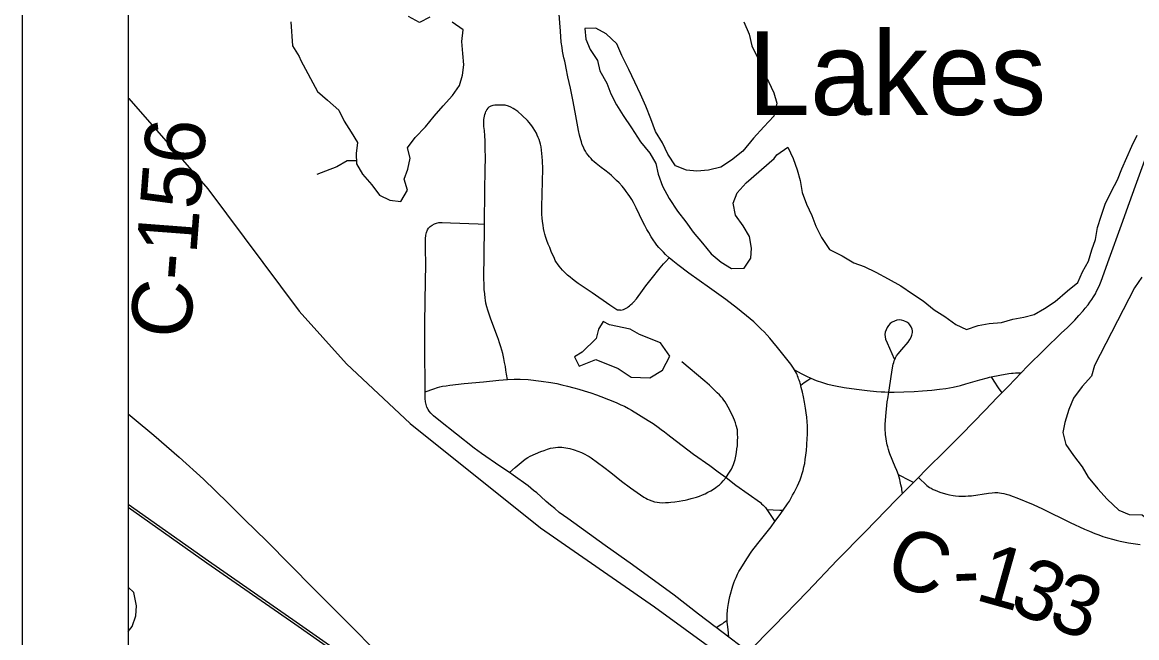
# Model space of a CAD drawing. Extents: x 0 to 34, y 0 to 22.
# Drawn here: x 2.014 to 3.067, y 16.327 to 16.909 of the extents above; entities that cross this region are included whole.
import ezdxf

# ---------------------------------------------------------------- set-up
doc = ezdxf.new("R2010")
doc.units = 0
for name, color, linetype in [('GM_X_Corporation', 7, 'Continuous'), ('GM_X_County_Road', 7, 'Continuous'), ('GM_X_County_Road_Text', 7, 'Continuous'), ('GM_X_Minor_Lake', 7, 'Continuous'), ('GM_X_Minor_River', 7, 'Continuous'), ('GM_X_Rail_Line', 7, 'Continuous'), ('GM_X_State_Route', 7, 'Continuous'), ('GM_X_Township_Road', 7, 'Continuous'), ('GM_X_Unincorporated_Text', 7, 'Continuous'), ('SH_Data', 7, 'Continuous')]:
    doc.layers.add(name, color=color, linetype=linetype)

msp = doc.modelspace()

# ---------------------------------------------------------------- linework, layer by layer
at = {"layer": 'GM_X_Corporation'}
msp.add_lwpolyline([(4.732, 17.2135), (3.7259, 17.2107), (3.5941, 17.2097), (3.4848, 17.2088), (3.0597, 17.2067), (2.6493, 17.2102), (2.5952, 17.2097), (2.159, 17.2055), (2.114, 17.2048), (2.114, 13.8173), (5.0539, 13.8173)], dxfattribs=at)
at = {"layer": 'GM_X_County_Road'}
for points in [[(2.114, 16.5387), (2.1198, 16.5341), (2.1385, 16.5187), (2.1622, 16.4977), (2.1852, 16.477), (2.2083, 16.4546), (2.2242, 16.439), (2.2452, 16.4184), (2.2893, 16.3739), (2.3285, 16.3343), (2.3433, 16.3193)], [(2.8611, 16.4786), (2.869, 16.4712), (2.8716, 16.4693), (2.873, 16.4685), (2.875, 16.4674), (2.8769, 16.4666), (2.879, 16.4657), (2.8813, 16.4649), (2.8844, 16.4638), (2.8879, 16.4629), (2.8905, 16.4622), (2.8937, 16.4616), (2.8961, 16.4612), (2.8993, 16.461), (2.9011, 16.4609), (2.9035, 16.4609), (2.9055, 16.4609), (2.908, 16.4612), (2.9112, 16.4614), (2.9272, 16.4638), (2.9307, 16.4641), (2.9333, 16.4644), (2.936, 16.4643), (2.9375, 16.4642), (2.9395, 16.4639), (2.9417, 16.4635), (2.944, 16.4628), (2.9464, 16.4622), (2.9504, 16.4607), (2.9539, 16.4594), (2.9694, 16.4531), (2.9784, 16.4489), (3.0044, 16.4361), (3.018, 16.4299), (3.0228, 16.4279), (3.0277, 16.4258), (3.0316, 16.4244), (3.0354, 16.423), (3.0398, 16.4217), (3.0443, 16.4203), (3.0478, 16.4194), (3.0516, 16.4185), (3.0565, 16.4176), (3.0595, 16.417), (3.0662, 16.4159), (3.0706, 16.4152)]]:
    msp.add_lwpolyline(points, dxfattribs=at)
at = {"layer": 'GM_X_Minor_Lake'}
for p, q in [((2.2772, 16.8725), (2.2929, 16.8434)), ((2.6982, 16.7571), (2.7245, 16.78)), ((3.0653, 16.6579), (3.0273, 16.5844)), ((2.5563, 16.61), (2.5431, 16.597))]:
    msp.add_line(p, q, dxfattribs=at)
for points in [[(2.2678, 16.9092), (2.2695, 16.8865), (2.2756, 16.8763), (2.2772, 16.8725)], [(2.2929, 16.8434), (2.3024, 16.8351), (2.3131, 16.8257), (2.3181, 16.8152), (2.325, 16.805), (2.3308, 16.7952), (2.3297, 16.7849), (2.3298, 16.7751), (2.3355, 16.7652), (2.3443, 16.7551), (2.3516, 16.7453), (2.3615, 16.7408), (2.3717, 16.7394), (2.378, 16.75), (2.3749, 16.7606), (2.3783, 16.7701), (2.3805, 16.7804), (2.3781, 16.7902), (2.3852, 16.7998), (2.395, 16.8101), (2.4032, 16.82), (2.4119, 16.8299), (2.4205, 16.8395), (2.4272, 16.849), (2.4302, 16.8589), (2.4312, 16.8684), (2.4304, 16.8794), (2.4296, 16.8907), (2.4306, 16.9017), (2.4203, 16.9089)], [(2.3991, 16.9136), (2.3893, 16.9086), (2.379, 16.9142)], [(2.6959, 16.9091), (2.7009, 16.8974), (2.7036, 16.8864), (2.709, 16.8754), (2.7133, 16.8626), (2.7194, 16.8528), (2.7244, 16.8422), (2.7271, 16.8324), (2.7242, 16.8202), (2.7148, 16.8099), (2.705, 16.7992), (2.6949, 16.787), (2.6844, 16.7786), (2.6742, 16.772), (2.6625, 16.7689), (2.6515, 16.7681), (2.6417, 16.7691), (2.6314, 16.7732), (2.6242, 16.7842), (2.6192, 16.7947), (2.6126, 16.8057), (2.608, 16.8174), (2.6034, 16.8295), (2.5984, 16.8408), (2.593, 16.8522), (2.5872, 16.8643), (2.5807, 16.8775), (2.576, 16.8885), (2.5658, 16.8979), (2.5562, 16.9031), (2.5457, 16.903), (2.5465, 16.8928), (2.5507, 16.8829), (2.5576, 16.8728), (2.56, 16.8629), (2.5665, 16.8512), (2.5704, 16.841), (2.5757, 16.8308), (2.5819, 16.8206), (2.5899, 16.8089), (2.5983, 16.7957), (2.6071, 16.7852), (2.6129, 16.7754), (2.6149, 16.7651), (2.6191, 16.7538), (2.6253, 16.7421), (2.6333, 16.7304), (2.6413, 16.7202), (2.6482, 16.7104), (2.657, 16.6999), (2.665, 16.6901), (2.6745, 16.6822), (2.6844, 16.6762), (2.6962, 16.6763), (2.7025, 16.6858), (2.7032, 16.6953), (2.7012, 16.7063), (2.6955, 16.7165), (2.6882, 16.7266), (2.6858, 16.738), (2.6896, 16.7475), (2.6982, 16.7571)], [(2.7245, 16.78), (2.7271, 16.7834), (2.7377, 16.7907), (2.7427, 16.7802), (2.7465, 16.7692), (2.7493, 16.7593), (2.7512, 16.748), (2.7551, 16.737), (2.7601, 16.7261), (2.764, 16.7162), (2.7694, 16.7053), (2.777, 16.694), (2.7888, 16.688), (2.7998, 16.6816), (2.8097, 16.6779), (2.8207, 16.6727), (2.8325, 16.6663), (2.8443, 16.6596), (2.8553, 16.6521), (2.8656, 16.6457), (2.8759, 16.6371), (2.8861, 16.6307), (2.8964, 16.6232), (2.9063, 16.6184), (2.9176, 16.6222), (2.9278, 16.6242), (2.9396, 16.6251), (2.9501, 16.6282), (2.9607, 16.6302), (2.9705, 16.6325), (2.9803, 16.6383), (2.9901, 16.6448), (3.0018, 16.6551), (3.0115, 16.6628), (3.016, 16.6731), (3.0216, 16.683), (3.0249, 16.6936), (3.0283, 16.7035), (3.0301, 16.7149), (3.0338, 16.7255), (3.0375, 16.7369), (3.0434, 16.7491), (3.049, 16.7598), (3.0531, 16.7704), (3.0628, 16.7917), (3.0676, 16.802)], [(3.0721, 16.6678), (3.0653, 16.6579)], [(2.5431, 16.597), (2.536, 16.5927), (2.5402, 16.5837), (2.556, 16.5902), (2.5773, 16.5817), (2.5895, 16.5734), (2.6073, 16.5728), (2.619, 16.5801), (2.626, 16.5934), (2.6172, 16.6059), (2.5975, 16.6137), (2.5887, 16.6189), (2.569, 16.623), (2.563, 16.6259), (2.5585, 16.6187), (2.5563, 16.61)], [(3.0273, 16.5844), (3.0247, 16.5745), (3.0157, 16.5646), (3.0075, 16.5535), (3.003, 16.5429), (2.9993, 16.5307), (2.9975, 16.5212), (3.0003, 16.5099), (3.0075, 16.4993), (3.0156, 16.4888), (3.0213, 16.479), (3.0305, 16.468), (3.0393, 16.4582), (3.0503, 16.4477), (3.0602, 16.4436), (3.0723, 16.4433), (3.0818, 16.4354), (3.0902, 16.4256), (3.0998, 16.4159), (3.1096, 16.4209)], [(2.114, 16.3332), (2.1179, 16.3377), (2.1212, 16.348), (2.1219, 16.3575), (2.1195, 16.37), (2.114, 16.375)]]:
    msp.add_lwpolyline(points, dxfattribs=at)
at = {"layer": 'GM_X_Minor_River'}
msp.add_lwpolyline([(2.3298, 16.7778), (2.3211, 16.778), (2.3113, 16.7723), (2.3007, 16.768), (2.2924, 16.7649)], dxfattribs=at)
at = {"layer": 'GM_X_Rail_Line'}
for points in [[(2.114, 16.8374), (2.1146, 16.8368), (2.1893, 16.7514), (2.2758, 16.6359), (2.3204, 16.5861), (2.3807, 16.5296), (2.5039, 16.4312), (2.6114, 16.3563), (2.7019, 16.2907), (2.7727, 16.25), (2.8225, 16.2263), (2.8815, 16.2027), (2.9759, 16.1869), (3.0752, 16.1606), (3.1383, 16.1243), (3.1826, 16.0961), (3.2121, 16.0625), (3.2578, 15.9657), (3.3033, 15.8368), (3.3342, 15.7629), (3.3516, 15.736), (3.4899, 15.62), (3.595, 15.5619), (3.6872, 15.5056)], [(3.6294, 15.4901), (3.5355, 15.5355), (3.4316, 15.5858), (3.3592, 15.6216), (3.2797, 15.6606), (3.2212, 15.6921), (3.1764, 15.7179), (3.1549, 15.731), (3.1291, 15.7467), (3.1033, 15.7631), (3.0624, 15.7903), (2.916, 15.893), (2.8198, 15.9595), (2.7679, 15.9959), (2.7008, 16.0427), (2.5976, 16.1149), (2.4486, 16.2192), (2.3494, 16.2884), (2.273, 16.3419), (2.1899, 16.3996), (2.114, 16.453)], [(3.6283, 15.488), (3.5345, 15.5334), (3.4306, 15.5837), (3.3582, 15.6195), (3.2786, 15.6585), (3.22, 15.6901), (3.1752, 15.7159), (3.1537, 15.729), (3.1279, 15.7448), (3.1021, 15.7611), (3.0611, 15.7884), (2.9146, 15.8911), (2.8185, 15.9575), (2.7665, 15.994), (2.6995, 16.0408), (2.5963, 16.113), (2.4473, 16.2173), (2.348, 16.2865), (2.2716, 16.34), (2.1886, 16.3977), (2.114, 16.4502)]]:
    msp.add_lwpolyline(points, dxfattribs=at)
at = {"layer": 'GM_X_State_Route'}
msp.add_lwpolyline([(2.7003, 16.3139), (2.7244, 16.3383), (2.7562, 16.371), (2.7843, 16.4004), (2.8107, 16.4274), (2.8404, 16.4577), (2.846, 16.4634), (2.8563, 16.4738), (2.8611, 16.4786), (2.8681, 16.4858), (2.8871, 16.5049), (2.9018, 16.5193), (2.9242, 16.5424), (2.9355, 16.5542), (2.9398, 16.5585), (2.9461, 16.5649), (2.9582, 16.5775), (2.9641, 16.5837), (2.9962, 16.6152), (3.0017, 16.6202), (3.0087, 16.6273), (3.0127, 16.6317), (3.0166, 16.636), (3.0186, 16.6385), (3.0213, 16.6418), (3.0231, 16.6443), (3.025, 16.6469), (3.0265, 16.6494), (3.0282, 16.6523), (3.0294, 16.6547), (3.0308, 16.6574), (3.0323, 16.6609), (3.0337, 16.6643), (3.0413, 16.6854), (3.053, 16.7175), (3.0605, 16.7386), (3.0663, 16.7543), (3.0787, 16.7888)], dxfattribs=at)
at = {"layer": 'GM_X_Township_Road'}
for p, q in [((2.7177, 16.4483), (2.7254, 16.437)), ((2.6818, 16.3278), (2.6699, 16.3368))]:
    msp.add_line(p, q, dxfattribs=at)
for points in [[(2.5943, 16.7334), (2.593, 16.736), (2.5916, 16.7385), (2.5901, 16.7414), (2.5883, 16.7441), (2.5867, 16.7465), (2.5849, 16.7489), (2.5834, 16.7509), (2.5809, 16.7538), (2.5781, 16.757), (2.5756, 16.7594), (2.5737, 16.7613), (2.5708, 16.7639), (2.5687, 16.7658), (2.5647, 16.7689), (2.5613, 16.7716), (2.5564, 16.7754), (2.5545, 16.777), (2.5531, 16.7783), (2.5516, 16.7799), (2.55, 16.7815), (2.5489, 16.7831), (2.5474, 16.7851), (2.5462, 16.7871), (2.5451, 16.789), (2.5443, 16.7909), (2.5433, 16.793), (2.5425, 16.7957), (2.5418, 16.7978), (2.5408, 16.8022), (2.5398, 16.8064), (2.5372, 16.8205), (2.5347, 16.8339), (2.5321, 16.8466), (2.5298, 16.8572), (2.5282, 16.8653), (2.5274, 16.8689), (2.5267, 16.8719), (2.526, 16.8751), (2.5253, 16.8784), (2.5247, 16.8815), (2.5242, 16.8848), (2.5235, 16.89), (2.5226, 16.9003), (2.521, 16.9201)], [(2.451, 16.718), (2.4513, 16.75), (2.4516, 16.769), (2.4517, 16.7813), (2.4517, 16.7839), (2.4516, 16.7863), (2.4516, 16.7892), (2.4515, 16.7927), (2.4514, 16.7969), (2.4512, 16.8016), (2.4508, 16.8064), (2.4504, 16.8103), (2.4503, 16.8154), (2.4503, 16.8169), (2.4505, 16.8185), (2.4508, 16.8202), (2.4511, 16.8216), (2.4517, 16.8232), (2.4522, 16.8246)], [(2.5795, 16.6368), (2.5781, 16.6368), (2.5767, 16.6369), (2.5759, 16.6372), (2.5751, 16.6376), (2.5741, 16.6383), (2.5693, 16.6416), (2.5525, 16.6532), (2.5395, 16.6619), (2.5368, 16.6639), (2.5341, 16.6659), (2.5318, 16.6678), (2.5294, 16.6698), (2.5268, 16.6724), (2.5246, 16.6746), (2.5231, 16.6763), (2.5214, 16.6783), (2.5198, 16.6805), (2.5189, 16.6818), (2.5178, 16.6838), (2.5169, 16.6855), (2.5139, 16.6923), (2.5125, 16.6958), (2.5112, 16.6991), (2.5098, 16.7026), (2.5089, 16.7055), (2.508, 16.7085), (2.5074, 16.7112), (2.5068, 16.7138), (2.5063, 16.7171), (2.5058, 16.7205), (2.5055, 16.7241), (2.5052, 16.7272), (2.5052, 16.7305), (2.5051, 16.7345), (2.5059, 16.7703), (2.5058, 16.7779), (2.5055, 16.7815), (2.5052, 16.7847), (2.5047, 16.788), (2.5043, 16.791), (2.5037, 16.7935), (2.5031, 16.7959), (2.5024, 16.7981), (2.5017, 16.8), (2.5008, 16.8021), (2.4999, 16.8041), (2.4985, 16.8065), (2.497, 16.809), (2.4957, 16.8108), (2.4945, 16.8126), (2.4931, 16.8142), (2.4915, 16.816), (2.4866, 16.8208), (2.4823, 16.8246), (2.4797, 16.8264), (2.4779, 16.8274), (2.4759, 16.8286), (2.4735, 16.8295), (2.4704, 16.8303), (2.4671, 16.8306), (2.4649, 16.8306), (2.4628, 16.8306), (2.4605, 16.8304), (2.4588, 16.83), (2.4569, 16.8295), (2.4551, 16.8286), (2.454, 16.8277), (2.453, 16.8263), (2.4522, 16.8246)], [(2.6255, 16.6863), (2.6221, 16.6894), (2.62, 16.6914), (2.6177, 16.6939), (2.6158, 16.696), (2.6139, 16.6983), (2.6126, 16.6999), (2.6102, 16.7033), (2.6084, 16.7061), (2.6061, 16.71), (2.6043, 16.7131), (2.6023, 16.7169), (2.6005, 16.7203), (2.5943, 16.7334)], [(2.3948, 16.5596), (2.3947, 16.5629), (2.3946, 16.6003), (2.3944, 16.6236), (2.3948, 16.6459), (2.3954, 16.6804), (2.3952, 16.6943), (2.3951, 16.7043), (2.3955, 16.7075), (2.3961, 16.7101), (2.397, 16.7125), (2.3981, 16.7142), (2.3994, 16.7157), (2.4015, 16.7172), (2.4037, 16.7184), (2.4056, 16.7191), (2.4076, 16.7195), (2.4108, 16.7196), (2.4189, 16.7193), (2.4449, 16.7183), (2.451, 16.718)], [(2.4727, 16.5713), (2.4718, 16.5763), (2.4712, 16.5801), (2.4706, 16.5836), (2.4699, 16.5873), (2.4692, 16.591), (2.4681, 16.5958), (2.4673, 16.5989), (2.4664, 16.602), (2.4651, 16.6058), (2.4641, 16.609), (2.4631, 16.6117), (2.4568, 16.6283), (2.4541, 16.6366), (2.4532, 16.64), (2.4523, 16.6433), (2.4518, 16.6461), (2.4515, 16.6482), (2.4511, 16.6522), (2.4507, 16.6563), (2.4505, 16.6614), (2.4503, 16.6662), (2.4509, 16.7136), (2.451, 16.718)], [(2.5795, 16.6368), (2.581, 16.6371), (2.5823, 16.6374), (2.5834, 16.6379), (2.5848, 16.6385), (2.5859, 16.6392), (2.5868, 16.6399), (2.5878, 16.6407), (2.589, 16.6417), (2.5904, 16.6431), (2.5917, 16.6444), (2.5946, 16.6476), (2.6001, 16.6552), (2.6035, 16.6597), (2.6085, 16.666), (2.617, 16.6767), (2.6202, 16.6805), (2.6219, 16.6824), (2.6255, 16.6863)], [(2.7439, 16.5803), (2.7429, 16.5819), (2.7416, 16.5838), (2.7403, 16.5856), (2.7391, 16.5872), (2.7365, 16.5904), (2.7279, 16.6014), (2.7235, 16.6067), (2.7204, 16.6104), (2.718, 16.6132), (2.7151, 16.6164), (2.7124, 16.6189), (2.7084, 16.6229), (2.7054, 16.6256), (2.702, 16.6286), (2.69, 16.6384), (2.6791, 16.6467), (2.6635, 16.6579), (2.6439, 16.6717), (2.6337, 16.6796), (2.6289, 16.6835), (2.6255, 16.6863)], [(2.833, 16.5594), (2.8336, 16.5633), (2.8362, 16.5803), (2.8372, 16.5858), (2.8377, 16.5874), (2.8381, 16.5888), (2.8386, 16.59), (2.8394, 16.5917), (2.8404, 16.5935), (2.8418, 16.5954), (2.8452, 16.5996), (2.8512, 16.6066), (2.8529, 16.609), (2.854, 16.6111), (2.8548, 16.6132), (2.8553, 16.6155), (2.8553, 16.6172), (2.8551, 16.6189), (2.8542, 16.621), (2.853, 16.623), (2.8519, 16.6242), (2.85, 16.6254), (2.8473, 16.6267), (2.8451, 16.6273), (2.8428, 16.6275), (2.8406, 16.6272), (2.8383, 16.6265), (2.8363, 16.6255), (2.8344, 16.6241), (2.8328, 16.6224), (2.8315, 16.6204), (2.8304, 16.6183), (2.8297, 16.6161), (2.8294, 16.6138), (2.8295, 16.6115), (2.83, 16.6092), (2.8314, 16.6059), (2.8359, 16.5957), (2.8381, 16.5908)], [(2.6792, 16.4787), (2.6813, 16.4818), (2.6832, 16.4846), (2.6843, 16.4866), (2.6853, 16.4888), (2.6861, 16.4908), (2.6869, 16.4928), (2.6878, 16.4957), (2.6884, 16.4988), (2.689, 16.5022), (2.6895, 16.5057), (2.6899, 16.5087), (2.6901, 16.5133), (2.6902, 16.5168), (2.6901, 16.5193), (2.6901, 16.5213), (2.6899, 16.5236), (2.6888, 16.5277), (2.688, 16.5302), (2.6871, 16.5329), (2.6861, 16.5351), (2.6849, 16.538), (2.6812, 16.5451), (2.6796, 16.5479), (2.6782, 16.5502), (2.6771, 16.5516), (2.6758, 16.5535), (2.6745, 16.5548), (2.673, 16.5566), (2.6709, 16.5587), (2.6684, 16.5611), (2.6661, 16.5635), (2.6634, 16.5659), (2.6612, 16.5679), (2.6592, 16.5696), (2.6373, 16.5879)], [(2.7439, 16.5803), (2.7503, 16.5769), (2.7551, 16.5743), (2.7593, 16.5724)], [(2.7497, 16.566), (2.7492, 16.5678), (2.7488, 16.5691), (2.7483, 16.5705), (2.7478, 16.5719), (2.7474, 16.5732), (2.7468, 16.5746), (2.7463, 16.5759), (2.7457, 16.5772), (2.7448, 16.5788), (2.7439, 16.5803)], [(2.3948, 16.5596), (2.403, 16.5625), (2.4065, 16.5637), (2.4086, 16.5642), (2.4113, 16.5648), (2.4147, 16.5653), (2.418, 16.5659), (2.4316, 16.5673), (2.4499, 16.5691), (2.4643, 16.5706), (2.4727, 16.5713)], [(2.4727, 16.5713), (2.4789, 16.5717), (2.4846, 16.5715), (2.492, 16.5711), (2.5044, 16.5697), (2.5136, 16.5683), (2.5191, 16.5674), (2.524, 16.5663), (2.5293, 16.565), (2.5352, 16.5634), (2.5401, 16.562), (2.5451, 16.5604), (2.5514, 16.5585), (2.5567, 16.5566), (2.5608, 16.5552), (2.5752, 16.5494), (2.5796, 16.5474), (2.5831, 16.5459), (2.5869, 16.5438), (2.5897, 16.5423), (2.6056, 16.5326), (2.6102, 16.5295), (2.615, 16.5261), (2.6178, 16.524), (2.6209, 16.5217), (2.624, 16.5194), (2.627, 16.5171), (2.6485, 16.5008), (2.6637, 16.4899), (2.6718, 16.4841), (2.6792, 16.4787)], [(2.7497, 16.566), (2.7531, 16.5683), (2.7566, 16.5706), (2.7593, 16.5724)], [(2.7593, 16.5724), (2.7644, 16.5703), (2.7702, 16.5685), (2.7751, 16.5669), (2.7825, 16.5652), (2.7907, 16.5637), (2.8026, 16.562), (2.8126, 16.5608), (2.8213, 16.56), (2.8258, 16.5597), (2.8291, 16.5595), (2.833, 16.5594)], [(2.833, 16.5594), (2.8381, 16.5592), (2.8471, 16.5595), (2.857, 16.5599), (2.865, 16.5606), (2.8738, 16.5612), (2.8808, 16.562), (2.8869, 16.5628), (2.8937, 16.5641), (2.9009, 16.5657), (2.9058, 16.5671), (2.9124, 16.569), (2.9189, 16.5709), (2.9263, 16.5729), (2.9281, 16.5733), (2.9296, 16.5736)], [(2.9296, 16.5736), (2.9379, 16.5754), (2.9463, 16.5769), (2.949, 16.5773), (2.9505, 16.5773), (2.9526, 16.5775), (2.9582, 16.5775)], [(2.9296, 16.5736), (2.9322, 16.5697), (2.9365, 16.5634), (2.9398, 16.5585)], [(2.4744, 16.4832), (2.4653, 16.4894), (2.448, 16.5013), (2.441, 16.5065), (2.4076, 16.5328), (2.4028, 16.5368), (2.4013, 16.5383), (2.4001, 16.5395), (2.3986, 16.5412), (2.3975, 16.543), (2.3964, 16.5452), (2.3956, 16.5476), (2.3951, 16.5501), (2.3949, 16.5533), (2.3948, 16.5596)], [(2.7332, 16.4477), (2.7373, 16.4536), (2.739, 16.4564), (2.7405, 16.4589), (2.7421, 16.4619), (2.7436, 16.4646), (2.7449, 16.467), (2.7466, 16.4706), (2.748, 16.4737), (2.7491, 16.4764), (2.7503, 16.4794), (2.7512, 16.4825), (2.752, 16.4853), (2.7528, 16.4886), (2.7535, 16.4919), (2.7541, 16.4957), (2.7547, 16.4998), (2.7551, 16.5041), (2.7555, 16.5091), (2.7556, 16.5107), (2.7558, 16.5144), (2.7561, 16.5202), (2.756, 16.524), (2.756, 16.5276), (2.7557, 16.5312), (2.7554, 16.5355), (2.7548, 16.5397), (2.7542, 16.544), (2.7532, 16.5497), (2.7523, 16.5548), (2.7513, 16.5593), (2.7508, 16.5615), (2.7503, 16.5638), (2.7499, 16.5652), (2.7497, 16.566)], [(2.8421, 16.4813), (2.8406, 16.4851), (2.8391, 16.4888), (2.8341, 16.5009), (2.8334, 16.503), (2.8328, 16.505), (2.8323, 16.5063), (2.832, 16.5077), (2.8315, 16.5094), (2.8311, 16.5111), (2.8308, 16.513), (2.8304, 16.5152), (2.8301, 16.5173), (2.8299, 16.5191), (2.8298, 16.521), (2.8296, 16.523), (2.8296, 16.5245), (2.8296, 16.5263), (2.8296, 16.5286), (2.8302, 16.5367), (2.8316, 16.5502), (2.8318, 16.5516), (2.832, 16.5529), (2.833, 16.5594)], [(2.4744, 16.4832), (2.48, 16.4881), (2.4873, 16.4943), (2.4894, 16.4959), (2.4917, 16.4974), (2.4942, 16.4988), (2.499, 16.5009), (2.5042, 16.5031), (2.5073, 16.5043), (2.5105, 16.5054), (2.5133, 16.5062), (2.5157, 16.5067), (2.5179, 16.507), (2.5201, 16.5072), (2.5221, 16.5072), (2.5241, 16.5072), (2.5277, 16.5068), (2.5316, 16.506), (2.5356, 16.5049), (2.5391, 16.5036), (2.5426, 16.5021), (2.5456, 16.5007), (2.5479, 16.4995), (2.5499, 16.4984), (2.5517, 16.4973), (2.5636, 16.4885), (2.5703, 16.4832), (2.5804, 16.4751), (2.5889, 16.4688), (2.6016, 16.4601), (2.6034, 16.4591), (2.6048, 16.4583), (2.6064, 16.4576), (2.6089, 16.4565), (2.6116, 16.4557), (2.614, 16.4552), (2.6163, 16.4549), (2.6191, 16.4547), (2.6219, 16.4549), (2.6247, 16.4551), (2.627, 16.4552), (2.6308, 16.4557), (2.635, 16.4562), (2.6383, 16.4568), (2.6404, 16.4572), (2.6432, 16.4579), (2.6463, 16.4587), (2.6488, 16.4593), (2.6512, 16.4601), (2.6542, 16.4611), (2.6569, 16.4623), (2.6593, 16.4633), (2.6621, 16.4647), (2.6648, 16.4661), (2.6673, 16.4677), (2.6696, 16.4691), (2.6712, 16.4703), (2.673, 16.4717), (2.6748, 16.4735), (2.6766, 16.4756), (2.6792, 16.4787)], [(2.6699, 16.3368), (2.6689, 16.3376), (2.653, 16.3496), (2.63, 16.3676), (2.5909, 16.3962), (2.565, 16.4144), (2.5298, 16.4399), (2.5257, 16.4428), (2.5216, 16.4457), (2.5174, 16.4492), (2.5134, 16.4524), (2.5093, 16.4561), (2.5042, 16.4606), (2.5004, 16.464), (2.4973, 16.4665), (2.4946, 16.4687), (2.492, 16.4706), (2.4781, 16.4807), (2.4744, 16.4832)], [(2.6792, 16.4787), (2.6885, 16.4715), (2.7116, 16.4549), (2.7127, 16.4539), (2.7144, 16.4525), (2.7164, 16.4502), (2.7177, 16.4483)], [(2.846, 16.4634), (2.8454, 16.467), (2.8452, 16.4687), (2.845, 16.4696), (2.8445, 16.4718), (2.8438, 16.4749), (2.8434, 16.4767), (2.8428, 16.4789), (2.8421, 16.4813)], [(2.8563, 16.4738), (2.8501, 16.477), (2.8453, 16.4796), (2.8421, 16.4813)], [(2.7177, 16.4483), (2.7236, 16.4481), (2.7299, 16.4478), (2.7332, 16.4477)], [(2.7254, 16.437), (2.7295, 16.4424), (2.7332, 16.4477)], [(2.6802, 16.3438), (2.6801, 16.3458), (2.6801, 16.3473), (2.6802, 16.349), (2.6802, 16.3505), (2.6804, 16.352), (2.6805, 16.3532), (2.6809, 16.3559), (2.6814, 16.3595), (2.6822, 16.3631), (2.6828, 16.3662), (2.6856, 16.3762), (2.6866, 16.379), (2.6875, 16.3815), (2.6887, 16.3842), (2.69, 16.3873), (2.6913, 16.3897), (2.693, 16.3928), (2.6987, 16.4018), (2.7036, 16.409), (2.7093, 16.4164), (2.7217, 16.432), (2.7254, 16.437)], [(2.6699, 16.3368), (2.6741, 16.3396), (2.676, 16.3408), (2.6775, 16.3419), (2.6802, 16.3438)], [(2.6818, 16.3278), (2.6811, 16.3351), (2.6806, 16.3396), (2.6803, 16.3418), (2.6802, 16.3438)], [(2.7003, 16.3139), (2.6935, 16.3191), (2.6818, 16.3278)]]:
    msp.add_lwpolyline(points, dxfattribs=at)
at = {"layer": 'SH_Data'}
for p, q in [((2.014, 20.7173), (2.014, 13.7173)), ((2.114, 20.6173), (2.114, 13.8173))]:
    msp.add_line(p, q, dxfattribs=at)

# ---------------------------------------------------------------- texts
at = {"layer": 'GM_X_County_Road_Text'}
for s, height, rotation, p in [('C-156', 0.05682, 85.646, (2.1725, 16.6089)), ('C', 0.0568, 339.5837, (2.8266, 16.3821)), ('1', 0.0568, 344.3127, (2.9132, 16.3635)), ('3', 0.0568, 335.6977, (2.9447, 16.3548)), ('-', 0.0568, 2.3286, (2.8945, 16.362)), ('3', 0.0568, 340.6369, (2.9816, 16.3384))]:
    msp.add_text(s, height=height, rotation=rotation, dxfattribs=at).set_placement(p)
at = {"layer": 'GM_X_Unincorporated_Text'}
msp.add_text('Lakes', height=0.07898, rotation=0, dxfattribs=at).set_placement((2.6999, 16.8212))

doc.saveas('drawing.dxf')
